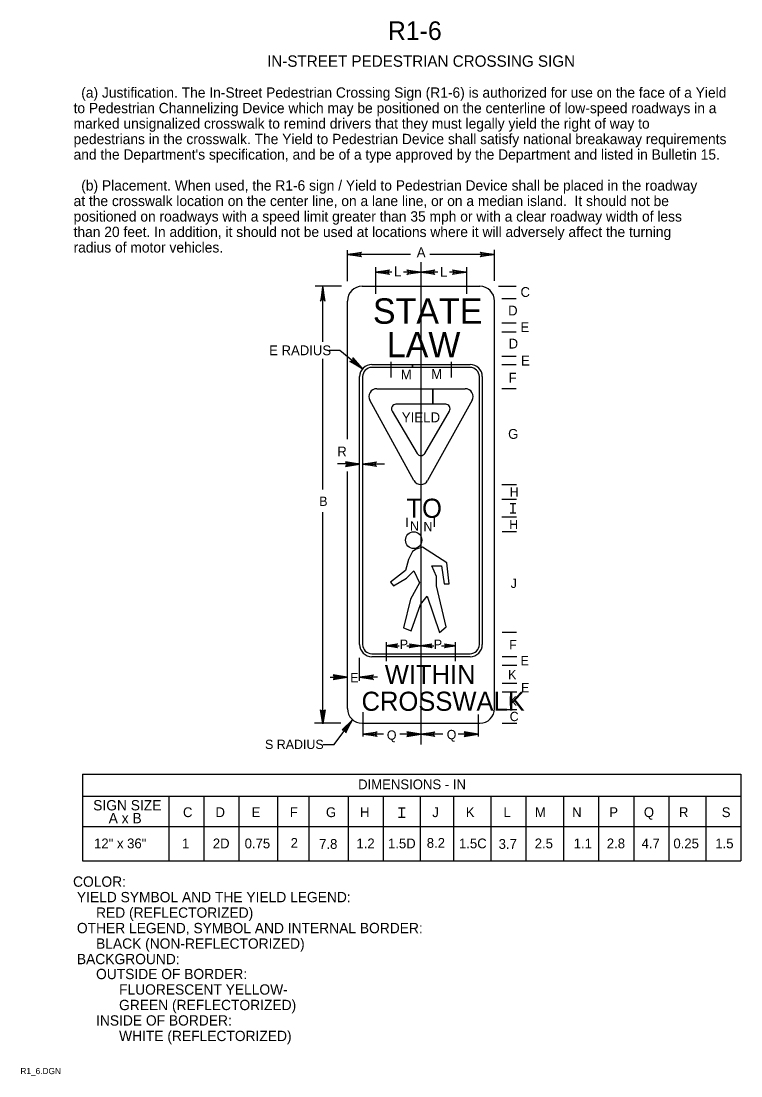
# Model space of a CAD drawing. Extents: x 0.013 to 0.187, y 0.004 to 0.259.
import ezdxf

# ---------------------------------------------------------------- set-up
doc = ezdxf.new("R2010")
doc.units = 0
for name, color, linetype in [('1', 7, 'Continuous'), ('2', 7, 'Continuous'), ('3', 7, 'Continuous')]:
    doc.layers.add(name, color=color, linetype=linetype)

# ---------------------------------------------------------------- blocks, each defined once
blk = doc.blocks.new('RARROW')
at = {"layer": '3'}
for p, q in [((-2.156, 0.28500000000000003), (-2.2665, 0.384625)), ((-2.2665, 0.384625), (0, 0)), ((0, 0), (-2.2665, -0.379125)), ((-2.156, 0.28500000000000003), (-2.075625, 0.12075)), ((0, 0), (-2.156, 0.28500000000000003)), ((-2.14975, -0.2705), (0, 0)), ((-2.075625, 0.12075), (0, 0)), ((0, 0), (-2.074, -0.108)), ((-2.2665, -0.379125), (-2.14975, -0.2705)), ((-2.074, -0.108), (-2.14975, -0.2705))]:
    blk.add_line(p, q, dxfattribs=at)

msp = doc.modelspace()

# ---------------------------------------------------------------- linework, layer by layer
at = {"layer": '1'}
for p, q in [((0.09862920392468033, 0.19980915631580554), (0.09862920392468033, 0.19337779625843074)), ((0.1096452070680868, 0.20107549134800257), (0.1096452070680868, 0.08423313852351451)), ((0.12066120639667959, 0.19980915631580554), (0.12066120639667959, 0.19337779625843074)), ((0.08999567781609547, 0.1797484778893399), (0.09538180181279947, 0.17531080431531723)), ((0.1023732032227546, 0.17689177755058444), (0.1023732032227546, 0.17309430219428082)), ((0.1169172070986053, 0.17689177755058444), (0.1169172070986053, 0.17309430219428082)), ((0.09774026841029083, 0.17626133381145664), (0.10762389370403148, 0.17626133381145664)), ((0.10762389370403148, 0.17554133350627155), (0.09774026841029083, 0.17554133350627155)), ((0.10762389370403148, 0.17626133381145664), (0.10762389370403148, 0.17554133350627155)), ((0.10762389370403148, 0.17554133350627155), (0.10762389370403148, 0.17626133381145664)), ((0.10762389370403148, 0.17626133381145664), (0.12155013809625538, 0.17626133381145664)), ((0.12155013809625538, 0.17554133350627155), (0.10762389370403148, 0.17554133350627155)), ((0.09478826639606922, 0.1084373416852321), (0.09478826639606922, 0.1733093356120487)), ((0.095508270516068, 0.1733093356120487), (0.095508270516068, 0.1084373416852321)), ((0.1237821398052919, 0.1084373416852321), (0.1237821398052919, 0.1733093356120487)), ((0.1245021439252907, 0.1733093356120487), (0.1245021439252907, 0.1084373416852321)), ((0.0989254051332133, 0.17038791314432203), (0.11249578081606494, 0.17038791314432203)), ((0.11249578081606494, 0.17038791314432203), (0.11249578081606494, 0.16660643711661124)), ((0.11249578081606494, 0.16660643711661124), (0.11249578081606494, 0.17038791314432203)), ((0.11249578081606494, 0.17038791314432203), (0.12036213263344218, 0.17038791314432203)), ((0.10794599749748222, 0.14818538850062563), (0.09726838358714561, 0.16758440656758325)), ((0.11249578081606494, 0.16660643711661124), (0.10358262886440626, 0.16660643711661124)), ((0.12201621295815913, 0.167579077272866), (0.11125709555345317, 0.14818005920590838)), ((0.11562648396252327, 0.16660643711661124), (0.11249578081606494, 0.16660643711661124)), ((0.10265282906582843, 0.16497701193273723), (0.10871360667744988, 0.15472030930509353)), ((0.11057628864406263, 0.15472555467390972), (0.1165593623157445, 0.16498225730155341)), ((0.10129320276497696, 0.1044088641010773), (0.10129320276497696, 0.10897585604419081)), ((0.11799720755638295, 0.1044088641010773), (0.11799720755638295, 0.10897585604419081)), ((0.09478826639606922, 0.09966362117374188), (0.09478826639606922, 0.10522556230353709)), ((0.09774026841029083, 0.10620533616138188), (0.12155013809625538, 0.10620533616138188)), ((0.12155013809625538, 0.10548533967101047), (0.09774026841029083, 0.10548533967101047)), ((0.09567720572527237, 0.0861904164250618), (0.09567720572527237, 0.09202206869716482)), ((0.08863192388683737, 0.08420225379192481), (0.09309222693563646, 0.0902057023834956)), ((0.12361320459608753, 0.0861904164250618), (0.12361320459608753, 0.09148818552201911))]:
    msp.add_line(p, q, dxfattribs=at)
for centre, radius, start, end in [((0.09774026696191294, 0.1733093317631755), 0.0029519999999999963, 90, 180), ((0.09774026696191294, 0.1733093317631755), 0.002231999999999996, 90, 180), ((0.12155014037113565, 0.1733093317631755), 0.0029519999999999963, 0, 90), ((0.12155014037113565, 0.1733093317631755), 0.002231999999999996, 0, 90), ((0.09892540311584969, 0.1684964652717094), 0.0018914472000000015, 89.99999999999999, 208.829273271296), ((0.12036213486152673, 0.1684964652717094), 0.0018914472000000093, 330.9862922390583, 90), ((0.10358262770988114, 0.1655264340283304), 0.0010800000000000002, 90, 210.57922687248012), ((0.1156264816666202, 0.1655264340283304), 0.0010800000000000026, 329.74356283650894, 90), ((0.10964340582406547, 0.1552697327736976), 0.0010800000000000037, 210.57922480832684, 329.7435707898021), ((0.109603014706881, 0.14909744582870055), 0.0018914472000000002, 208.82927195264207, 330.9862956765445), ((0.09774026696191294, 0.10843733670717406), 0.0029519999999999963, 180, 270), ((0.09774026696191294, 0.10843733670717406), 0.002231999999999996, 180, 270), ((0.12155014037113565, 0.10843733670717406), 0.002231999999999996, 270, 0), ((0.12155014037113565, 0.10843733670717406), 0.0029519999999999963, 270, 0)]:
    msp.add_arc(centre, radius, start, end, dxfattribs=at)
at = {"layer": '3'}
for p, q in [((0.09182935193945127, 0.1964127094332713), (0.09181839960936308, 0.20398147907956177)), ((0.09181983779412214, 0.2029866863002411), (0.10710689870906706, 0.2029866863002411)), ((0.11178574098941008, 0.2029866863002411), (0.12744340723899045, 0.2029866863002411)), ((0.127452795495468, 0.19649794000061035), (0.1274418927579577, 0.20403303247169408)), ((0.09862920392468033, 0.19872915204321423), (0.10260959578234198, 0.19872915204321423)), ((0.1053738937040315, 0.19872915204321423), (0.1096452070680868, 0.19872915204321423)), ((0.1096452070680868, 0.19872915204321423), (0.11376362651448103, 0.19872915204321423)), ((0.11653389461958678, 0.19872915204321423), (0.12066120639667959, 0.19872915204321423)), ((0.0903842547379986, 0.19520458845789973), (0.08397648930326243, 0.19521385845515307)), ((0.08590953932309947, 0.18173327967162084), (0.08590953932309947, 0.19521220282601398)), ((0.09540039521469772, 0.19519733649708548), (0.1238900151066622, 0.19519733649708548)), ((0.12839683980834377, 0.1952038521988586), (0.13273180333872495, 0.19521012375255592)), ((0.09183626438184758, 0.15818688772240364), (0.09183626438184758, 0.19163320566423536)), ((0.12745414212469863, 0.09292146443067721), (0.12745414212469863, 0.19163320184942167)), ((0.12922180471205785, 0.1922530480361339), (0.13273180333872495, 0.19225812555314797)), ((0.12922180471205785, 0.18634904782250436), (0.13273180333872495, 0.1863541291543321)), ((0.12922180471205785, 0.18418905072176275), (0.13273180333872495, 0.18419412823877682)), ((0.08735499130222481, 0.1797484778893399), (0.08999567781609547, 0.1797484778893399)), ((0.08590953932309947, 0.14593905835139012), (0.08590953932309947, 0.17758861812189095)), ((0.12922180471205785, 0.1782850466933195), (0.13273180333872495, 0.17829012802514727)), ((0.12922471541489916, 0.17627243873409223), (0.1327347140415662, 0.17627752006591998)), ((0.12922180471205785, 0.17040073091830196), (0.13273180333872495, 0.17040580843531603)), ((0.0947358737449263, 0.15220432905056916), (0.08944250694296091, 0.15221198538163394)), ((0.095508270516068, 0.15220432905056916), (0.10080163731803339, 0.15221198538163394)), ((0.09183626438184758, 0.09292146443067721), (0.09183626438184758, 0.15030164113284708)), ((0.12925539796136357, 0.14718021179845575), (0.13276540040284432, 0.14718528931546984)), ((0.1292605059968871, 0.1436522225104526), (0.1327705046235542, 0.14365730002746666)), ((0.13128261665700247, 0.14254696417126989), (0.132586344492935, 0.14254884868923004)), ((0.08590953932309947, 0.08937220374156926), (0.08590953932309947, 0.14050697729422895)), ((0.10633320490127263, 0.13692827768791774), (0.10633320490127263, 0.13909964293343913)), ((0.11295720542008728, 0.13692827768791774), (0.11295720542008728, 0.13909964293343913)), ((0.12926675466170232, 0.13933222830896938), (0.13277675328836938, 0.13933730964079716)), ((0.13128571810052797, 0.14032588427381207), (0.13258944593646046, 0.14032776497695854)), ((0.12927186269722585, 0.13580423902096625), (0.13278186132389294, 0.13580931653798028)), ((0.12930716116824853, 0.11140579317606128), (0.1328171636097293, 0.11141087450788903)), ((0.10129320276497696, 0.10807614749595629), (0.10438389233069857, 0.10807614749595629)), ((0.10621884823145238, 0.10807614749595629), (0.1096452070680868, 0.10807614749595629)), ((0.1096452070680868, 0.10807614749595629), (0.11275389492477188, 0.10807614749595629)), ((0.11461501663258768, 0.10807614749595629), (0.11799720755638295, 0.10807614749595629)), ((0.1293157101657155, 0.10549791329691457), (0.1328257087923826, 0.10550299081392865)), ((0.12931873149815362, 0.10340932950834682), (0.13282873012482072, 0.10341441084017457)), ((0.0876202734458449, 0.10052438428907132), (0.09183626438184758, 0.10053048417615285)), ((0.09912228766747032, 0.1005239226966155), (0.09478826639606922, 0.10053019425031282)), ((0.12932498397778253, 0.0990875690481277), (0.13283498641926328, 0.09909264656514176)), ((0.12932800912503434, 0.09699632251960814), (0.1328380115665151, 0.09700140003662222)), ((0.12933426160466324, 0.09267633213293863), (0.13284426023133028, 0.0926814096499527)), ((0.09023113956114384, 0.08936481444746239), (0.08382337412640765, 0.08937408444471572)), ((0.09540039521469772, 0.08935733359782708), (0.1238900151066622, 0.08935733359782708)), ((0.12933905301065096, 0.08936521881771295), (0.13284905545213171, 0.08937029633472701)), ((0.09567720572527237, 0.0868064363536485), (0.10060389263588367, 0.0868064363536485)), ((0.10451057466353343, 0.0868064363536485), (0.1096452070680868, 0.0868064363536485)), ((0.1096452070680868, 0.0868064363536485), (0.11491389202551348, 0.0868064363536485)), ((0.11867659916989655, 0.0868064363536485), (0.12361320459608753, 0.0868064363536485)), ((0.08599123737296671, 0.08420225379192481), (0.08863192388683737, 0.08420225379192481)), ((0.027625, 0.077), (0.187125, 0.077)), ((0.027672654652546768, 0.07700778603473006), (0.027672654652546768, 0.05600778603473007)), ((0.18713278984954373, 0.07700778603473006), (0.18713278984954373, 0.05600778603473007)), ((0.18713278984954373, 0.07165619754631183), (0.027672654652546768, 0.07165619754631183)), ((0.04855717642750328, 0.07162013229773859), (0.04855717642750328, 0.05600778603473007)), ((0.05705717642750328, 0.07162013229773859), (0.05705717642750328, 0.05600778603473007)), ((0.06555717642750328, 0.07162013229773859), (0.06555717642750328, 0.05600778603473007)), ((0.07488844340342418, 0.07162013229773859), (0.07488844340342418, 0.05600778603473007)), ((0.08251943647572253, 0.07162013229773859), (0.08251943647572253, 0.05600778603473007)), ((0.09198156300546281, 0.07162013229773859), (0.09198156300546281, 0.05600778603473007)), ((0.10048156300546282, 0.07162013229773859), (0.10048156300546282, 0.05600778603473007)), ((0.10944981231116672, 0.07162013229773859), (0.10944981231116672, 0.05600778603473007)), ((0.11748156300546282, 0.07162013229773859), (0.11748156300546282, 0.05600778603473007)), ((0.12657128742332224, 0.07162013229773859), (0.12657128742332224, 0.05600778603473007)), ((0.13507128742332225, 0.07162013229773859), (0.13507128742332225, 0.05600778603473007)), ((0.14416101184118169, 0.07162013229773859), (0.14416101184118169, 0.05600778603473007)), ((0.15266101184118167, 0.07162013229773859), (0.15266101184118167, 0.05600778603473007)), ((0.16116101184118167, 0.07162013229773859), (0.16116101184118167, 0.05600778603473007)), ((0.16966101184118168, 0.07165619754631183), (0.16966101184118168, 0.05600778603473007)), ((0.17863278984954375, 0.07165619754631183), (0.17863278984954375, 0.05600778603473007)), ((0.1042092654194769, 0.0688861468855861), (0.1057855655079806, 0.0688861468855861)), ((0.1042092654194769, 0.06663770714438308), (0.1057855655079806, 0.06663770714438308)), ((0.027625, 0.064375), (0.187125, 0.064375)), ((0.027625, 0.056), (0.187125, 0.056))]:
    msp.add_line(p, q, dxfattribs=at)
msp.add_lwpolyline([(0.10225000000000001, 0.1235), (0.10300000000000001, 0.122625), (0.106125, 0.1245), (0.107875, 0.12625), (0.10925, 0.123375), (0.107125, 0.11937500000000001), (0.105375, 0.1125), (0.10725, 0.11175), (0.1095, 0.11812500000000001), (0.111125, 0.120125), (0.114125, 0.111375), (0.11575, 0.11275), (0.113375, 0.122625), (0.113375, 0.12325), (0.113375, 0.12375), (0.113375, 0.123875), (0.113375, 0.124375), (0.113375, 0.124875), (0.11225, 0.1275), (0.114625, 0.1275), (0.11525, 0.123125), (0.1165, 0.123125), (0.115875, 0.12825), (0.11, 0.132), (0.1085, 0.1315), (0.107625, 0.131), (0.106625, 0.129), (0.105875, 0.12637500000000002)], close=True, dxfattribs=at)
for centre, start, end in [((0.09540039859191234, 0.19163320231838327), 90, 180), ((0.12389001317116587, 0.19163320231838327), 0, 90), ((0.0954003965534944, 0.09292146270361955), 180, 270), ((0.12389001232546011, 0.09292146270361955), 270, 0)]:
    msp.add_arc(centre, 0.0035641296, start, end, dxfattribs=at)
msp.add_ellipse((0.1078815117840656, 0.13370482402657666), major_axis=(1.2524159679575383e-19, 0.002045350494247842), ratio=0.9570312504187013, dxfattribs=at)

# ---------------------------------------------------------------- block references
for p, xscale, yscale, rotation in [((0.091875, 0.202875), 0.0014890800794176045, 0.0014729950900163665, 180), ((0.098625, 0.198625), 0.0014890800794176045, 0.0014729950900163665, 180), ((0.109625, 0.198625), 0.0014890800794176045, 0.0014729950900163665, 180), ((0.085875, 0.195), 0.0014890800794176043, -0.0014729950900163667, 90.08291713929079), ((0.095375, 0.17525000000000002), 0.0014890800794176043, 0.0014729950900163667, -40.02844404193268), ((0.09475, 0.152125), 0.0014890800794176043, -0.0014729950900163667, 0.08291713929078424), ((0.0955, 0.152125), 0.0014890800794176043, 0.0014729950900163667, 179.91708286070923), ((0.10125, 0.108125), 0.0011793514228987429, 0.0012962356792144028, 180), ((0.109625, 0.108125), 0.0011793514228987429, 0.0012962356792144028, 180), ((0.09175, 0.1005), 0.0014890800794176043, -0.0014729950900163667, 0.08291713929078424), ((0.09475, 0.1005), 0.0014890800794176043, 0.0014729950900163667, 179.91708286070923), ((0.085875, 0.08925), 0.0014890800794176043, 0.0014729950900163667, -90.08291713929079), ((0.093, 0.090125), 0.0014890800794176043, -0.0014729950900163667, 53.63944611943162), ((0.095625, 0.08675000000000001), 0.0014890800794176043, 0.0014729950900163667, 179.91708286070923), ((0.109625, 0.08675000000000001), 0.0014890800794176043, -0.0014729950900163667, 0.08291713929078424), ((0.109625, 0.08675000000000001), 0.0014890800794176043, 0.0014729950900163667, 179.91708286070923), ((0.1235, 0.08675000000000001), 0.0014890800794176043, -0.0014729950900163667, 0.08291713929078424)]:
    msp.add_blockref('RARROW', p, dxfattribs=dict(at, xscale=xscale, yscale=yscale, rotation=rotation))
for p, xscale, yscale in [((0.12737500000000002, 0.202875), 0.0014890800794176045, 0.0014729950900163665), ((0.109625, 0.198625), 0.0014890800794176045, 0.0014729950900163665), ((0.120625, 0.198625), 0.0014890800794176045, 0.0014729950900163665), ((0.1095, 0.108125), 0.0011793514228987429, 0.0012962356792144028), ((0.11800000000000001, 0.108125), 0.0011793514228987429, 0.0012962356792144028)]:
    msp.add_blockref('RARROW', p, dxfattribs=dict(at, xscale=xscale, yscale=yscale))

# ---------------------------------------------------------------- texts
at = {"layer": '1'}
for s, height, p in [('R1-6', 0.0045000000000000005, (0.10162500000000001, 0.2548646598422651)), ('IN-STREET PEDESTRIAN CROSSING SIGN', 0.00275025, (0.072375, 0.24836465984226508)), ('STATE', 0.006156, (0.098, 0.186125)), ('LAW', 0.006146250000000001, (0.101375, 0.178)), ('TO', 0.004626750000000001, (0.106125, 0.139125)), ('WITHIN', 0.004626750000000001, (0.100875, 0.098875)), ('CROSSWALK', 0.004626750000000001, (0.09525, 0.092375)), ('COLOR:', 0.0024997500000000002, (0.025375, 0.04975)), (' YIELD SYMBOL AND THE YIELD LEGEND:', 0.0024997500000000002, (0.025375, 0.046)), ('      RED (REFLECTORIZED)', 0.0024997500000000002, (0.025375, 0.04225)), (' OTHER LEGEND, SYMBOL AND INTERNAL BORDER:', 0.0024997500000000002, (0.025375, 0.0385)), ('      BLACK (NON-REFLECTORIZED)', 0.0024997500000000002, (0.025375, 0.03475)), (' BACKGROUND:', 0.0024997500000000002, (0.025375, 0.031)), ('      OUTSIDE OF BORDER:', 0.0024997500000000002, (0.025375, 0.027375)), ('            FLUORESCENT YELLOW-', 0.0024997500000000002, (0.025375, 0.023625)), ('            GREEN (REFLECTORIZED)', 0.0024997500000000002, (0.025375, 0.019875)), ('      INSIDE OF BORDER:', 0.0024997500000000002, (0.025375, 0.016125)), ('            WHITE (REFLECTORIZED)', 0.0024997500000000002, (0.025375, 0.012375)), ('R1_6.DGN', 0.0015, (0.012625, 0.004375))]:
    msp.add_text(s, height=height, dxfattribs=at).set_placement(p)
at = {"layer": '2'}
for s, p in [('  (a) Justification. The In-Street Pedestrian Crossing Sign (R1-6) is authorized for use on the face of a Yield', (0.025500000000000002, 0.24087525)), ('to Pedestrian Channelizing Device which may be positioned on the centerline of low-speed roadways in a ', (0.025500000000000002, 0.2371255)), ('marked unsignalized crosswalk to remind drivers that they must legally yield the right of way to', (0.025500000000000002, 0.23337575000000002)), ('pedestrians in the crosswalk. The Yield to Pedestrian Device shall satisfy national breakaway requirements', (0.025500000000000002, 0.229626)), ("and the Department's specification, and be of a type approved by the Department and listed in Bulletin 15.", (0.025500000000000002, 0.22587625)), ('  (b) Placement. When used, the R1-6 sign / Yield to Pedestrian Device shall be placed in the roadway', (0.025500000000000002, 0.21837675)), ('at the crosswalk location on the center line, on a lane line, or on a median island.  It should not be ', (0.025500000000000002, 0.214627)), ('positioned on roadways with a speed limit greater than 35 mph or with a clear roadway width of less ', (0.025500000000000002, 0.21087725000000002)), ('than 20 feet. In addition, it should not be used at locations where it will adversely affect the turning', (0.025500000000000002, 0.2071275)), ('radius of motor vehicles.', (0.025500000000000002, 0.20337775))]:
    msp.add_text(s, height=0.0024997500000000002, dxfattribs=at).set_placement(p)
at = {"layer": '3'}
for s, height, p in [('A', 0.0023752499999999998, (0.108625, 0.20225)), ('L', 0.0023752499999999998, (0.10312500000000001, 0.197625)), ('L', 0.0023752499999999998, (0.11425, 0.1975)), ('C', 0.0023752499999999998, (0.13375, 0.192625)), ('D', 0.0023752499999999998, (0.13075, 0.18812500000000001)), ('E', 0.0023752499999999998, (0.13375, 0.184125)), ('D', 0.0023752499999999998, (0.130875, 0.180125)), ('E RADIUS', 0.0023752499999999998, (0.072875, 0.1785)), ('E', 0.0023752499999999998, (0.133875, 0.176)), ('M', 0.0023752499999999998, (0.10475, 0.172625)), ('M', 0.0023752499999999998, (0.112125, 0.17275000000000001)), ('F', 0.0023752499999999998, (0.130875, 0.171875)), ('YIELD', 0.0024, (0.105, 0.16225)), ('G', 0.0023752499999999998, (0.13075, 0.15825)), ('R', 0.0023752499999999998, (0.089375, 0.154)), ('H', 0.00224925, (0.131125, 0.14425)), ('B', 0.00224925, (0.085, 0.14200000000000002)), ('I', 0.00224925, (0.1315, 0.140375)), ('N', 0.0022500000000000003, (0.107, 0.136)), ('N', 0.0022500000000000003, (0.11025, 0.135875)), ('H', 0.00224925, (0.131, 0.136375)), ('J', 0.00224925, (0.131375, 0.122125)), ('P', 0.00224925, (0.1045, 0.107375)), ('P', 0.00224925, (0.11275, 0.107375)), ('F', 0.00224925, (0.131, 0.10725)), ('E', 0.00224925, (0.13375, 0.10337500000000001)), ('K', 0.00224925, (0.13075, 0.1)), ('E', 0.0022500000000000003, (0.0925, 0.09925)), ('E', 0.00224925, (0.133875, 0.096875)), ('K', 0.00224925, (0.130875, 0.093625)), ('C', 0.0022500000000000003, (0.131125, 0.089875)), ('Q', 0.00224925, (0.101375, 0.085375)), ('Q', 0.00224925, (0.115875, 0.0855)), ('S RADIUS', 0.00224925, (0.07187500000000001, 0.083125)), ('DIMENSIONS - IN', 0.0023752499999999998, (0.09441729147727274, 0.073375)), ('SIGN SIZE', 0.0024997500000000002, (0.03025, 0.06825)), ('C', 0.0023752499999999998, (0.052000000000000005, 0.066625)), ('D', 0.0023752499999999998, (0.059875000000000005, 0.066625)), ('E', 0.0023752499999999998, (0.068625, 0.066625)), ('F', 0.0023752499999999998, (0.077875, 0.066625)), ('G', 0.0023752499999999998, (0.08662500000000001, 0.066625)), ('H', 0.0023752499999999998, (0.094875, 0.066625)), ('I', 0.0023752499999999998, (0.1045, 0.066625)), ('J', 0.0023752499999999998, (0.112375, 0.066625)), ('K', 0.0023752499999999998, (0.1205, 0.066625)), ('L', 0.0023752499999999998, (0.129625, 0.066625)), ('M', 0.0023752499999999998, (0.13725, 0.066625)), ('N', 0.0023752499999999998, (0.14625, 0.066625)), ('P', 0.0023752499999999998, (0.15525, 0.066625)), ('Q', 0.0023752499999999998, (0.163625, 0.066625)), ('R', 0.0023752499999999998, (0.172125, 0.066625)), ('S', 0.0023752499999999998, (0.1825, 0.066625)), ('A x B', 0.0024997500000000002, (0.034, 0.065125)), ('12" x 36"', 0.0023752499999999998, (0.03046134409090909, 0.05906237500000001)), ('1', 0.0023752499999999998, (0.051768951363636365, 0.05906237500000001)), ('2D', 0.0023752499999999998, (0.05922156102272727, 0.05906237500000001)), ('0.75', 0.0023752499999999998, (0.06693568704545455, 0.05906237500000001)), ('2', 0.0023752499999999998, (0.07807353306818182, 0.05918737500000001)), ('7.8', 0.0023752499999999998, (0.08498055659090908, 0.05893737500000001)), ('1.2', 0.0023752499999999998, (0.09401090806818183, 0.05906237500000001)), ('1.5D', 0.0023752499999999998, (0.10165893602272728, 0.05906237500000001)), ('8.2', 0.0023752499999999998, (0.11104497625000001, 0.05918737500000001)), ('1.5C', 0.0023752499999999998, (0.11885195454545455, 0.05906237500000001)), ('3.7', 0.0023752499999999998, (0.12845342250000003, 0.05893737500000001)), ('2.5', 0.0023752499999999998, (0.13719505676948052, 0.05906237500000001)), ('1.1', 0.0023752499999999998, (0.14664305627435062, 0.05906237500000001)), ('2.8', 0.0023752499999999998, (0.15465432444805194, 0.05906237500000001)), ('4.7', 0.0023752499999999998, (0.1630779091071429, 0.05906237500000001)), ('0.25', 0.0023752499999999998, (0.1707842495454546, 0.05906237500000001)), ('1.5', 0.0023752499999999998, (0.18093639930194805, 0.05906237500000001))]:
    msp.add_text(s, height=height, dxfattribs=at).set_placement(p)

doc.saveas('drawing.dxf')
